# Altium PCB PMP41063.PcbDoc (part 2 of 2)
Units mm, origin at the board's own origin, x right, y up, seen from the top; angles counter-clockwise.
Board outline 173.28 x 60.81 mm, 2 copper layers (Top Layer, Bottom Layer), stack 1.575 mm thick; 103 components, 53 nets, 215 pads, 774 vias.
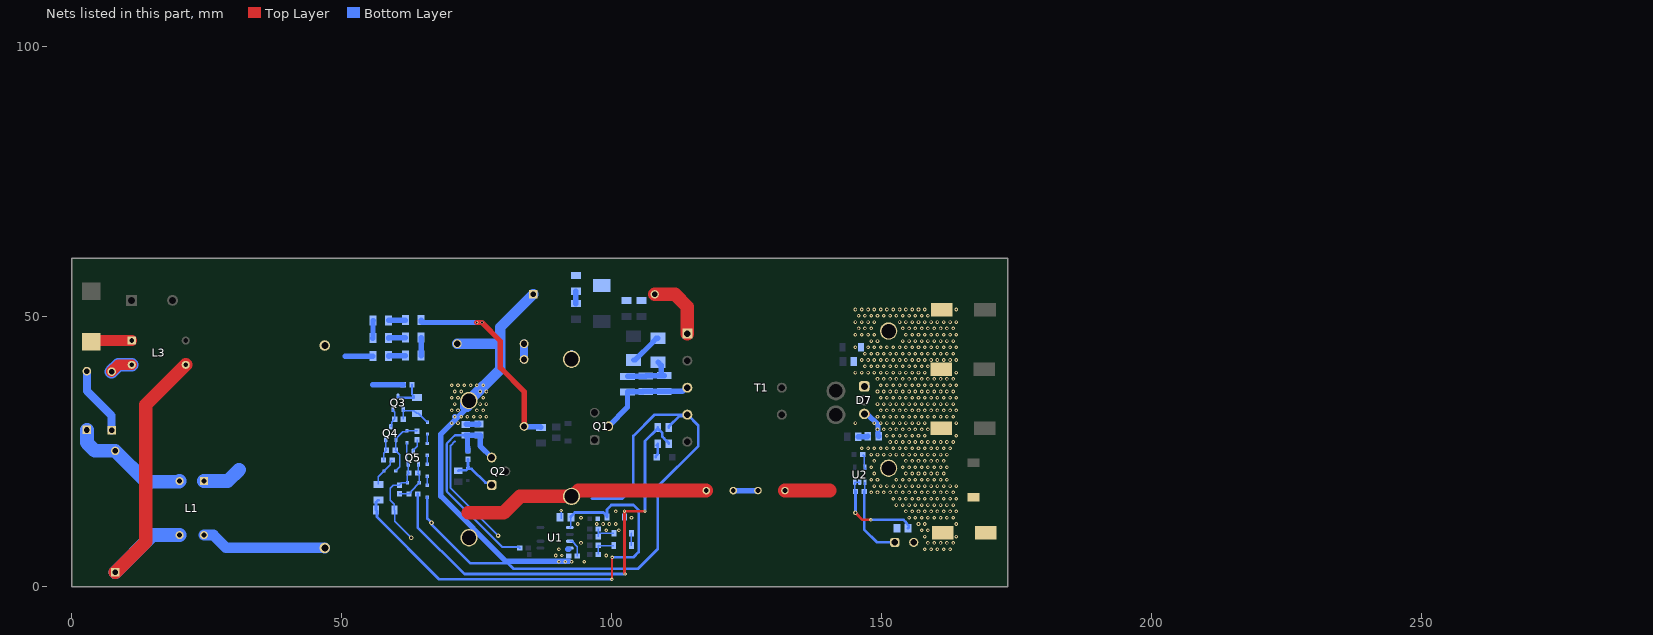
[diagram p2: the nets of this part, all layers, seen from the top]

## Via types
v1: diameter 0.66, hole 0.33, Top Layer to Bottom Layer, 760 vias
v2: diameter 0.61, hole 0.203, Top Layer to Bottom Layer, tented both sides, 8 vias
v3: diameter 0.864, hole 0.406, Top Layer to Bottom Layer, tented both sides, 4 vias
v4: diameter 0.6, hole 0.3, Top Layer to Bottom Layer, 2 vias

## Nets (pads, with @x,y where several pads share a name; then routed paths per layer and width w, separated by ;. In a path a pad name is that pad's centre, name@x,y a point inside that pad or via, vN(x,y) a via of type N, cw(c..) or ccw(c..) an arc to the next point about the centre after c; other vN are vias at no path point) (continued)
NetC9_2: C9.2 C17.1 | length 4.6
  Bottom Layer w1: C9.2@122.485,17.776 122.489,17.779 127.058,17.779 C17.1@127.061,17.782
NetC10_1: C10.1 Q3.3 R45.2 | length 5.7
  Bottom Layer w0.4: Q3.3@60.4,35.221 60.4,35.088 60.5,34.988 63.351,34.988 63.351,35.236 62.972,35.616 R45.2@62.972,37.393
NetC10_2: C10.2 D13.1 Q3.1 R38.1 | length 7.6
  Bottom Layer w0.254: R38.1@61.353,30.982 61.35,30.986 Q3.1@61.35,32.782 ; D13.1@65.867,30.442 65.715,30.595 65.618,30.595 65.256,30.957 65.256,30.981 64.149,32.088 C10.2@63.874,32.088 63.351,32.611 Q3.1@61.521,32.611 ; Q3.1@61.35,32.782 Q3.1@61.35,32.821 Q3.1@61.35,32.782 ; Q3.1@61.35,32.782 Q3.1@61.521,32.611 ; Q3.1@61.35,32.782 Q3.1@61.521,32.611
NetC16_2: C16.2 R27.2 | length 1.8
  Bottom Layer w1: R27.2@145.623,27.73 145.677,27.784 147.34,27.784 C16.2@147.394,27.838
NetC25_1: C25.1 D20.1 Q5.1 R9.2 R42.2 | length 8.3
  Bottom Layer w0.254: R9.2@60.66,17.186 62.403,17.186 R42.2@62.426,17.163 62.451,17.163 62.799,17.511 62.799,17.683 D20.1@64.326,19.21 64.326,20.734 C25.1@64.026,21.034 64.176,21.184 Q5.1@64.176,22.683
NetC33_1: C33.1 L1.3 L3.3 | length 58.6
  Top Layer w2.54: C33.1@8.02,2.633 13.665,8.278 13.665,33.668 L3.3@21.072,41.075
  Bottom Layer w2.54: C33.1@8.02,2.633 14.948,9.561 18.955,9.561 18.981,9.535 L1.3@19.935,9.535
NetC33_2: C33.2 D9.1 L1.2 | length 22.6
  Bottom Layer w2.54: D9.1@2.769,29.014 2.769,26.62 4.256,25.133 C33.2@8.02,25.133 13.721,19.431 19.831,19.431 L1.2@19.935,19.535
NetD1_2: D1.2 D2.1 | length 6.2
  Bottom Layer w1: D1.2@104.018,41.964 104.31,41.964 107.668,45.322 107.668,45.399 108.247,45.978 D2.1@108.539,45.978
NetD2_2: D2.2 R16.2 R17.2 R18.2 | length 10.2
  Bottom Layer w1: R17.2@102.9,38.944 103.674,38.944 103.712,38.982 106.266,38.982 106.329,39.046 109.027,39.046 R16.2@109.052,39.071 ; R16.2@109.682,39.071 109.261,39.071 109.111,39.221 D2.2@109.111,40.987 ; D2.2@109.111,40.987 D2.2@108.539,41.558 D2.2@109.111,40.987
NetD4_1: D4.1 R34.2 | length 3.2
  Bottom Layer w0.254: R34.2@108.113,26.046 R34.2@108.503,26.435
  Bottom Layer w0.5: D4.1@108.113,23.98 108.113,24.132 108.503,24.522 R34.2@108.503,26.435
NetD5_1: D5.1 R35.1 R36.2 | length 4.6
  Bottom Layer w0.254: R35.1@97.487,5.964 R36.2@97.487,7.659 97.54,7.607 D5.1@100.352,7.607
NetD5_2: D5.2 D12.2 | length 2.3
  Bottom Layer w0.254: D5.2@103.627,7.607 103.627,9.851 D12.2@103.652,9.876
NetD6_1: D6.1 R21.1 R22.1 | length 38.2
  Top Layer w1: v4(75.006,48.911) 75.904,48.911 79.324,45.491 79.324,40.55 83.746,36.129 D6.1@83.746,29.676
  Bottom Layer w1: R21.1@64.677,49.336 64.677,49.061 64.827,48.911 v4(75.006,48.911) v4(75.946,48.912) ; D6.1@83.746,29.676 83.831,29.591 86.777,29.591 R22.1@86.862,29.507
NetD6_2: D6.2 D10.1 | length 2.9
  Bottom Layer w1.5: D6.2@83.746,42.076 83.748,42.078 83.748,44.915 83.751,44.918 D10.1@83.751,44.985
NetD9_2: D9.2 D21.1 | length 12.8
  Bottom Layer w1.5: D9.2@2.769,39.89 2.769,36.246 7.341,31.674 D21.1@7.341,28.938
NetD11_2: D11.2 Q2.1 R26.2 R28.1 | length 9.4
  Bottom Layer w0.5: R26.2@71.558,21.455 71.633,21.529 72.985,21.529 D11.2@73.312,21.856 ; R28.1@73.335,23.585 73.335,22.335 73.447,22.222 73.362,22.137 73.362,21.906 D11.2@73.312,21.856 ; Q2.1@77.749,18.816 77.31,19.254 76.591,19.254 74.039,21.806 73.362,21.806 D11.2@73.312,21.856
NetD13_2: D13.2 D14.1 | length 1.8
  Bottom Layer w0.254: D14.1@65.791,26.505 65.829,26.543 65.829,28.204 D13.2@65.867,28.242
NetD14_2: D14.2 D17.1 | length 1.7
  Bottom Layer w0.254: D14.2@65.791,24.305 65.804,24.293 65.804,22.657 D17.1@65.816,22.644
NetD16_1: D16.1 D19.2 Q4.1 R39.1 R41.1 | length 11.3
  Bottom Layer w0.254: D19.2@59.989,21.413 60.736,22.161 60.736,24.385 60.233,24.888 60.233,24.913 59.885,25.261 R39.1@59.86,25.261 60.01,25.411 60.01,27.418 61.264,28.671 61.859,28.671 D16.1@62.032,28.844 63.865,28.844 R41.1@63.911,28.798
NetD17_2: D17.2 D18.1 | length 1.7
  Bottom Layer w0.254: D18.1@65.816,18.758 D17.2@65.816,20.444
NetD19_1: D19.1 R40.1 R43.1 | length 5.6
  Bottom Layer w0.254: R43.1@56.759,18.908 56.759,20.383 58.937,22.561 58.937,23.085 59.285,23.433 R40.1@59.31,23.433
NetD21_2: D21.2 L3.2 | length 8.5
  Top Layer w2: D21.2@7.341,39.814 8.601,41.075 L3.2@11.072,41.075
  Bottom Layer w2.54: D21.2@7.341,39.814 8.601,41.075 L3.2@11.072,41.075
NetF1_1: F1.1 L3.1 | length 7.6
  Top Layer w2: F1.1@3.556,45.32 3.811,45.575 L3.1@11.072,45.575
NetQ2_3: Q2.3 R28.2 R29.2 R32.2 R33.2 | length 52.5
  Bottom Layer w0.254: 69.478,17.678 69.478,26.444 69.478,26.563 ; 70.824,27.909 72.843,27.909 R32.2@72.954,28.02
  Bottom Layer w0.4: 69.478,26.444 69.429,26.395 69.429,17.727 69.478,17.678 69.478,17.575 79.713,7.34 82.735,7.34 R29.2@82.948,7.126 ; 69.478,26.563 70.824,27.909 70.935,28.02 R32.2@72.954,28.02
  Bottom Layer w1: R32.2@72.954,28.02 72.992,28.058 R32.2@73.081,28.058 ; R28.2@73.335,25.185 73.335,25.804 73.254,25.885 73.254,27.885 R32.2@73.081,28.058 ; Q2.3@77.749,23.896 75.595,26.049 75.595,28.058 R32.2@73.081,28.058
NetQ3_2: Q3.2 Q4.3 R38.2 | length 3.6
  Bottom Layer w0.254: Q4.3@59.06,29.63 59.219,29.789 59.219,30.473 59.728,30.982 R38.2@59.753,30.982 59.753,32.305 59.45,32.608 Q3.2@59.45,32.821
NetQ4_2: Q4.2 R39.2 R40.2 | length 4.1
  Bottom Layer w0.254: R40.2@57.71,23.433 57.71,24.736 58.235,25.261 R39.2@58.26,25.261 58.11,25.411 Q4.2@58.11,27.23
NetQ5_3: Q5.3 R41.2 | length 2.4
  Bottom Layer w0.254: Q5.3@63.226,25.083 63.226,25.283 63.911,25.969 R41.2@63.911,27.198
NetR1_1: R1.1 R5.2 | length 2.3
  Bottom Layer w1: R5.2@93.331,52.412 93.331,52.557 93.326,52.562 93.326,54.691 R1.1@93.333,54.698
NetR4_1: R4.1 R6.2 | length 3.2
  Bottom Layer w1: R4.1@58.656,42.672 58.711,42.727 61.706,42.727 R6.2@61.761,42.782
NetR6_1: R6.1 R10.2 | length 3.3
  Bottom Layer w1: R6.1@64.661,42.782 R10.2@64.661,46.106
NetR10_1: R10.1 R13.2 | length 3.2
  Bottom Layer w1: R13.2@58.626,46.023 58.667,46.065 61.72,46.065 R10.1@61.761,46.106
NetR12_2: R12.2 U1.3 | length 3.6
  Bottom Layer w0.254: U1.3@92.216,8.397 92.641,8.397 93.62,7.418 R12.2@93.62,5.634
NetR13_1: R13.1 R19.2 | length 3.3
  Bottom Layer w1: R13.1@55.726,46.023 55.749,46.046 55.749,49.255 R19.2@55.772,49.278
NetR19_1: R19.1 R21.2 | length 3.1
  Bottom Layer w1: R19.1@58.672,49.278 58.701,49.307 61.747,49.307 R21.2@61.777,49.336
NetR31_1: R31.1 U2.5 | length 3
  Bottom Layer w0.254: R31.1@146.442,24.444 146.703,24.183 146.703,22.282 U2.5@146.876,22.109 146.876,21.909 U2.5@147.049,21.736
PGND: C3.2 C6.2 C8.1 C9.1 C19.1 C24.2 C25.2 C26.1 C27.1 D10.2 D12.1 D16.2 D18.2 D20.2 HS1.1 HS1.2 HS2.1 HS2.2 L1.4 Q5.2 R3.1 R9.1 R12.1 R32.1 R33.1 R137.1 T1.4 U1.4 | length 321.9
  Top Layer w1.5: HS1.1@73.538,9.316 HS1.1@73.594,9.372
  Top Layer w2.54: HS1.2@73.233,34.32 HS1.2@73.332,34.419 ; 73.404,13.649 79.921,13.649 82.979,16.707 HS2.1@92.53,16.707 92.708,16.707 93.777,17.776 C9.1@117.485,17.776
  Bottom Layer w0.254: C3.2@59.71,14.174 59.71,15.235 58.937,16.008 58.937,18.235 59.488,18.786 R9.1@60.66,18.786 60.66,18.811 61.059,19.21 D20.2@62.126,19.21 62.126,20.734 C25.2@62.426,21.034 62.276,21.184 Q5.2@62.276,22.683 62.276,22.896 62.032,23.14 D16.2@62.032,26.644 ; C3.2@59.753,14.13 59.753,12.13 v3(62.837,9.046) ; C24.2@90.612,12.572 v2(90.612,14.093) ; R137.1@97.486,9.217 97.486,9.941 ; R3.1@97.486,10.666 97.486,9.941 ; D12.1@100.377,9.876 97.551,9.876 97.486,9.941
  Bottom Layer w0.4: 70.917,26.893 70.129,26.105 70.129,18.241 v3(78.928,9.443)
  Bottom Layer w0.5: D18.2@65.816,16.558 65.816,12.618 v3(66.604,11.831) 66.673,11.761 66.673,11.411 73.791,4.293 80.407,4.293 ; 80.407,4.685 81.79,3.302 104.826,3.302 108.503,6.979 108.503,18.511 116.018,26.026 116.018,29.791 T1.4@113.975,31.834 ; 96.317,16.304 101.954,16.304 103.98,18.33 103.98,27.871 107.943,31.834 T1.4@113.975,31.834 ; C6.2@110.532,29.457 110.532,29.622 112.486,31.576 113.717,31.576 T1.4@113.975,31.834
  Bottom Layer w1: v1(70.333,30.287) v1@70.354,30.266 ; v1(70.917,31.455) 71.23,31.142 ; 72.387,33.092 72.387,34.419 73.246,33.56 73.246,33.092 72.63,33.092 72.63,32.543 71.23,31.142 ; R32.1@72.992,30.09 75.354,30.09 R33.1@75.392,30.128 ; U1.4@91.848,6.922 U1.4@92.011,6.922 ; 92.003,4.685 91.364,4.685 C19.1@84.689,4.685 80.407,4.685 68.326,16.766 68.326,28.238 v1@70.354,30.266 ; HS2.2@92.584,43.273 HS2.2@92.605,43.273 ; v1@70.354,30.266 71.23,31.142
  Bottom Layer w1.5: D10.2@71.351,44.985 D10.2@71.351,45.025 ; HS1.2@73.246,33.092 73.538,33.384 HS1.2@73.538,34.446
  Bottom Layer w2: L1.4@24.435,9.535 26.188,9.535 28.541,7.182 46.804,7.182 C27.1@46.837,7.15 ; D10.2@71.351,44.985 79.146,44.985 ; HS1.2@73.308,34.676 HS1.2@73.538,34.446 79.324,40.232 79.324,48.034 C26.1@85.424,54.134
  other v1: 90.195,4.582 91.364,4.582 92.532,4.582 94.869,4.582 89.611,5.75 98.958,5.75 90.195,6.919 94.285,8.087 98.958,10.424 101.295,10.424 93.701,11.592 97.206,11.592 98.374,11.592 99.543,11.592 100.711,11.592 94.285,12.761 103.632,12.761 100.711,13.929 71.501,30.287 72.085,31.455 73.254,31.455 74.422,31.455 75.59,31.455 76.759,31.455 70.333,32.624 71.501,32.624 75.006,32.624 76.175,32.624 70.917,33.792 75.59,33.792 76.759,33.792 70.333,34.96 71.501,34.96 76.175,34.96 70.917,36.129 72.085,36.129 75.59,36.129 76.759,36.129 70.333,37.297 71.501,37.297 72.669,37.297 73.838,37.297 75.006,37.297 76.175,37.297
  other v2: 90.739,5.761
SGND: C11.2 C12.2 C13.2 C16.1 C17.2 C18.2 C20.2 C21.2 C22.2 D7.1 D7.3 HS3.1 HS3.2 J1.2 R30.1 U2.2 U2.3 | length 33.8
  Top Layer w0.5: v3(145.106,13.672) 146.419,12.359 v2(147.976,12.359)
  Top Layer w1: D7.3@146.758,31.987 D7.3@147.292,31.987
  Top Layer w2.54: C17.2@132.061,17.782 140.303,17.782
  Bottom Layer w0.254: C12.2@145.126,17.631 144.976,17.781 U2.3@144.976,19.359 U2.2@145.926,19.359 ; HS3.1@151.457,46.922 HS3.1@151.457,47.379
  Bottom Layer w0.5: v3@145.126,13.672 C12.2@145.126,17.631 ; v2(147.976,12.359) 154.009,12.359 154.438,11.929 154.438,11.878 154.975,11.34 154.975,10.899 R30.1@154.866,10.79 ; J1.2@155.859,8.134 J1.2@155.908,8.183
  Bottom Layer w1: D7.3@146.758,31.987 147.292,31.987 149.291,29.988 149.291,27.973 C16.1@149.426,27.838 ; D7.1@146.758,37.067 D7.1@147.292,37.067 ; J1.2@155.774,8.317 J1.2@155.908,8.183
  other v1: 157.963,6.919 159.131,6.919 160.299,6.919 161.468,6.919 162.636,6.919 158.547,8.087 159.715,8.087 160.884,8.087 162.052,8.087 163.22,8.087 157.963,9.256 163.805,9.256 157.378,10.424 158.547,10.424 156.794,11.592 157.963,11.592 163.805,11.592 155.042,12.761 156.21,12.761 157.378,12.761 158.547,12.761 159.715,12.761 160.884,12.761 162.052,12.761 163.22,12.761 154.457,13.929 155.626,13.929 156.794,13.929 157.963,13.929 159.131,13.929 160.299,13.929 161.468,13.929 162.636,13.929 163.805,13.929 152.705,15.098 153.873,15.098 155.042,15.098 156.21,15.098 157.378,15.098 158.547,15.098 159.715,15.098 160.884,15.098 162.052,15.098 163.22,15.098 152.121,16.266 153.289,16.266 154.457,16.266 155.626,16.266 156.794,16.266 157.963,16.266 159.131,16.266 160.299,16.266 161.468,16.266 162.636,16.266 163.805,16.266 148.031,17.434 149.2,17.434 150.368,17.434 151.536,17.434 152.705,17.434 153.873,17.434 155.042,17.434 156.21,17.434 157.378,17.434 158.547,17.434 159.715,17.434 160.884,17.434 162.052,17.434 163.22,17.434 148.615,18.603 149.784,18.603 150.952,18.603 152.121,18.603 153.289,18.603 154.457,18.603 155.626,18.603 156.794,18.603 157.963,18.603 159.131,18.603 160.299,18.603 161.468,18.603 162.636,18.603 163.805,18.603 148.031,19.771 149.2,19.771 152.705,19.771 153.873,19.771 155.042,19.771 156.21,19.771 157.378,19.771 158.547,19.771 159.715,19.771 160.884,19.771 162.052,19.771 148.615,20.94 154.457,20.94 155.626,20.94 156.794,20.94 157.963,20.94 159.131,20.94 160.299,20.94 161.468,20.94 148.031,22.108 153.873,22.108 155.042,22.108 156.21,22.108 157.378,22.108 158.547,22.108 159.715,22.108 160.884,22.108 162.052,22.108 148.615,23.276 154.457,23.276 155.626,23.276 156.794,23.276 157.963,23.276 159.131,23.276 160.299,23.276 161.468,23.276 148.031,24.445 149.2,24.445 150.368,24.445 151.536,24.445 152.705,24.445 153.873,24.445 155.042,24.445 156.21,24.445 157.378,24.445 158.547,24.445 159.715,24.445 160.884,24.445 162.052,24.445 146.279,25.613 147.447,25.613 148.615,25.613 149.784,25.613 150.952,25.613 152.121,25.613 153.289,25.613 154.457,25.613 155.626,25.613 156.794,25.613 157.963,25.613 159.131,25.613 160.299,25.613 161.468,25.613 162.636,25.613 151.536,26.782 152.705,26.782 153.873,26.782 155.042,26.782 156.21,26.782 157.378,26.782 158.547,26.782 159.715,26.782 160.884,26.782 162.052,26.782 163.22,26.782 150.952,27.95 152.121,27.95 153.289,27.95 154.457,27.95 155.626,27.95 156.794,27.95 157.963,27.95 163.805,27.95 149.2,29.118 150.368,29.118 151.536,29.118 152.705,29.118 153.873,29.118 155.042,29.118 156.21,29.118 157.378,29.118 158.547,29.118 145.11,30.287 148.615,30.287 149.784,30.287 150.952,30.287 152.121,30.287 153.289,30.287 154.457,30.287 155.626,30.287 156.794,30.287 157.963,30.287 163.805,30.287 149.2,31.455 150.368,31.455 151.536,31.455 152.705,31.455 153.873,31.455 155.042,31.455 156.21,31.455 157.378,31.455 158.547,31.455 159.715,31.455 160.884,31.455 162.052,31.455 163.22,31.455 149.784,32.624 150.952,32.624 152.121,32.624 153.289,32.624 154.457,32.624 155.626,32.624 156.794,32.624 157.963,32.624 159.131,32.624 160.299,32.624 161.468,32.624 162.636,32.624 163.805,32.624 149.2,33.792 150.368,33.792 151.536,33.792 152.705,33.792 153.873,33.792 155.042,33.792 156.21,33.792 157.378,33.792 158.547,33.792 159.715,33.792 160.884,33.792 162.052,33.792 163.22,33.792 149.784,34.96 150.952,34.96 152.121,34.96 153.289,34.96 154.457,34.96 155.626,34.96 156.794,34.96 157.963,34.96 159.131,34.96 160.299,34.96 161.468,34.96 162.636,34.96 163.805,34.96 149.2,36.129 150.368,36.129 151.536,36.129 152.705,36.129 153.873,36.129 155.042,36.129 156.21,36.129 157.378,36.129 158.547,36.129 159.715,36.129 160.884,36.129 162.052,36.129 163.22,36.129 149.784,37.297 150.952,37.297 152.121,37.297 153.289,37.297 154.457,37.297 155.626,37.297 156.794,37.297 157.963,37.297 159.131,37.297 160.299,37.297 161.468,37.297 162.636,37.297 163.805,37.297 149.2,38.466 150.368,38.466 151.536,38.466 152.705,38.466 153.873,38.466 155.042,38.466 156.21,38.466 157.378,38.466 158.547,38.466 159.715,38.466 160.884,38.466 162.052,38.466 163.22,38.466 145.11,39.634 146.279,39.634 147.447,39.634 148.615,39.634 149.784,39.634 150.952,39.634 152.121,39.634 153.289,39.634 154.457,39.634 155.626,39.634 156.794,39.634 157.963,39.634 163.805,39.634 146.863,40.802 148.031,40.802 149.2,40.802 150.368,40.802 151.536,40.802 152.705,40.802 153.873,40.802 155.042,40.802 156.21,40.802 157.378,40.802 158.547,40.802 146.279,41.971 147.447,41.971 148.615,41.971 149.784,41.971 150.952,41.971 152.121,41.971 153.289,41.971 154.457,41.971 155.626,41.971 156.794,41.971 157.963,41.971 159.131,41.971 160.299,41.971 161.468,41.971 162.636,41.971 163.805,41.971 146.863,43.139 148.031,43.139 149.2,43.139 150.368,43.139 151.536,43.139 152.705,43.139 153.873,43.139 155.042,43.139 156.21,43.139 157.378,43.139 158.547,43.139 159.715,43.139 160.884,43.139 162.052,43.139 163.22,43.139 145.11,44.308 147.447,44.308 148.615,44.308 149.784,44.308 150.952,44.308 152.121,44.308 153.289,44.308 154.457,44.308 155.626,44.308 156.794,44.308 157.963,44.308 159.131,44.308 160.299,44.308 161.468,44.308 162.636,44.308 163.805,44.308 148.031,45.476 149.2,45.476 153.873,45.476 155.042,45.476 156.21,45.476 157.378,45.476 158.547,45.476 159.715,45.476 160.884,45.476 162.052,45.476 163.22,45.476 145.11,46.644 146.279,46.644 147.447,46.644 148.615,46.644 154.457,46.644 155.626,46.644 156.794,46.644 157.963,46.644 159.131,46.644 160.299,46.644 161.468,46.644 162.636,46.644 163.805,46.644 145.694,47.813 146.863,47.813 148.031,47.813 153.873,47.813 155.042,47.813 156.21,47.813 157.378,47.813 158.547,47.813 159.715,47.813 160.884,47.813 162.052,47.813 163.22,47.813 145.11,48.981 146.279,48.981 147.447,48.981 148.615,48.981 153.289,48.981 154.457,48.981 155.626,48.981 156.794,48.981 157.963,48.981 159.131,48.981 160.299,48.981 161.468,48.981 162.636,48.981 163.805,48.981 145.694,50.15 146.863,50.15 148.031,50.15 149.2,50.15 150.368,50.15 151.536,50.15 152.705,50.15 153.873,50.15 155.042,50.15 156.21,50.15 157.378,50.15 158.547,50.15 145.11,51.318 146.279,51.318 147.447,51.318 148.615,51.318 149.784,51.318 150.952,51.318 152.121,51.318 153.289,51.318 154.457,51.318 155.626,51.318 156.794,51.318 157.963,51.318 163.805,51.318
SW: Q1.2 R16.1 R17.1 R18.1 T1.3 | length 19.2
  Bottom Layer w1: Q1.2@99.348,29.671 102.9,33.223 102.9,35.944 R17.1@102.9,36.044 102.939,36.082 105.76,36.082 105.848,36.171 R16.1@109.682,36.171 113.083,36.171 113.745,36.834 T1.3@113.975,36.834
Vaux_rec: C6.1 D15.2 R34.1 R42.1 | length 84.9
  Top Layer w0.5: v2(102.464,2.311) 102.464,2.341 102.357,2.448 v2(102.357,13.972) v2(106.146,13.972)
  Bottom Layer w0.254: D15.2@102.357,12.893 v2(102.357,13.972)
  Bottom Layer w0.5: R42.1@64.026,17.163 64.026,10.981 72.695,2.311 v2(102.464,2.311) ; v2(106.146,13.972) 106.146,26.937 C6.1@108.5,29.292 ; C6.1@108.5,29.457 C6.1@108.5,29.292 ; R34.1@110.535,26.435 110.535,26.6 109.688,27.447 109.688,27.463 109.347,27.804 109.347,28.445 C6.1@108.5,29.292
VDD: C3.1 C24.1 D15.1 R43.2 U1.1 | length 86.2
  Top Layer w0.4: v2(100,1.347) 100,5.201 100.031,5.232 100.031,5.381 v2(100.071,5.421)
  Bottom Layer w0.254: C24.1@92.41,12.831 U1.1@92.41,11.097 ; U1.1@92.25,10.937 U1.1@92.216,10.937 U1.1@92.25,10.937 ; U1.1@92.25,10.937 U1.1@92.41,11.097 ; U1.1@92.25,10.937 U1.1@92.41,11.097
  Bottom Layer w0.5: C3.1@56.31,14.174 56.499,13.985 56.499,12.877 68.029,1.347 v2(100,1.347) ; C3.1@56.369,14.304 56.31,14.363 56.31,15.608 56.71,16.008 R43.2@56.759,16.008 ; C24.1@92.41,12.831 92.41,12.996 93.141,13.726 98.401,13.726 98.874,13.253 99.082,13.045 D15.1@99.082,12.893 ; D15.1@99.082,13.253 99.082,14.276 99.897,15.091 101.28,15.091 104.009,15.091 104.954,14.147 104.954,6.377 104.004,5.427 100.078,5.427 v2(100.071,5.421)
VIN: C1.1 C2.1 C26.2 C27.2 D22.2 L1.1 R1.2 R4.2 R45.1 T1.1 | length 30.8
  Top Layer w2.54: C26.2@107.924,54.134 111.675,54.134 113.975,51.834 T1.1@113.975,46.834
  Bottom Layer w1: 50.571,42.672 R4.2@55.756,42.672 ; 55.726,37.393 R45.1@61.372,37.393 ; T1.1@113.55,47.259 T1.1@113.975,46.834
  Bottom Layer w2.54: L1.1@24.435,19.535 28.857,19.535 30.937,21.615
VOUT: C12.1 C22.1 J1.1 L2.2 R30.2 U2.1 | length 15.5
  Bottom Layer w0.254: C12.1@146.726,17.631 146.876,17.781 U2.1@146.876,19.359
  Bottom Layer w0.5: C12.1@146.726,17.631 146.726,10.61 149.154,8.183 J1.1@152.408,8.183
pads on no net: T1.2 T1.7 T1.8 U1.8 U2.4
copper on no net: | length 927.9
  Top Layer w0.381: 199.885,78.054 210.297,78.054 233.913,78.054 255.751,78.054 272.256,78.054 286.731,78.054 ; 199.885,81.102 210.297,81.102 233.913,81.102 255.751,81.102 272.256,81.102 286.731,81.102 ; 199.885,84.15 210.297,84.15 233.913,84.15 255.751,84.15 272.256,84.15 286.731,84.15 ; 199.885,87.198 210.297,87.198 233.913,87.198 255.751,87.198 272.256,87.198 286.731,87.198 ; 199.885,90.246 210.297,90.246 233.913,90.246 255.751,90.246 272.256,90.246 286.731,90.246 ; 199.885,93.294 210.297,93.294 233.913,93.294 255.751,93.294 272.256,93.294 286.731,93.294 ; 199.885,96.342 286.731,96.342 ; 210.297,99.39 210.297,75.006 ; 233.913,99.39 233.913,75.006 ; 255.751,99.39 255.751,75.006 ; 272.256,99.39 272.256,75.006 ; 210.297,75.006 199.885,75.006 199.885,99.39 286.731,99.39 286.731,75.006 272.256,75.006 ; 210.297,75.006 233.913,75.006 ; 233.913,75.006 255.751,75.006 ; 255.751,75.006 272.256,75.006

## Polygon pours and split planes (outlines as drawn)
PGND on Top Layer "TOP_LAYER_PGND_P010" (solid, remove dead copper, pour order 10): 29.693,58.725 30.404,59.436 93.927,59.436 96.332,57.792 96.332,39.236 88.206,39.292 88.206,49.488 84.961,52.732 75.078,52.728 72.387,49.602 72.387,42.384 77.521,37.19 77.521,30.121 72.387,25.385 72.387,18.392 79.934,9.794 79.934,1.753 29.693,1.753
FLYB on Top Layer "TOP_LAYER_FLYB_P000" (solid, remove dead copper, pour order 0): 139.275,32.691 140.317,33.733 142.479,33.733 144.385,35.639 147.984,35.639 148.285,35.339 148.285,33.733 147.948,33.396 145.228,33.396 143.547,31.715 143.547,30.823 142.687,29.963 140.168,29.963 139.275,30.856
FLYA on Top Layer "TOP_LAYER_FLYA_P001" (solid, remove dead copper, pour order 1): 139.172,58.577 140.771,60.176 170.878,60.176 172.547,58.508 172.547,21.416 172.623,21.34 171.836,20.552 164.572,20.552 163.708,21.416 163.708,24.87 165.232,26.394 165.232,52.094 163.932,53.395 144.815,53.395 143.591,52.171 143.591,37.494 143.591,35.511 142.277,34.196 139.77,34.196 139.172,34.794
SGND on Top Layer "TOP_LAYER_SGND_P002" (solid, remove dead copper, pour order 2): 144.203,51.784 144.203,31.472 142.719,29.988 139.319,29.988 139.319,16.667 150.48,16.667 154.716,12.491 154.716,9.148 154.716,7.421 155.58,6.557 162.844,6.557 164.521,8.233 164.521,18.47 162.844,20.146 162.844,25.239 164.521,26.915 164.521,51.79 163.374,52.937 145.357,52.937
VOUT on Top Layer "TOP_LAYER_VOUT_P009" (solid, remove dead copper, pour order 9): 165.232,18.47 165.232,8.335 162.987,6.09 154.98,6.09 153.947,7.124 153.947,10.156 153.583,10.519 150.652,10.519 150.043,9.91 150.043,2.747 151.821,0.969 169.549,0.969 172.623,4.044 172.623,18.432 172.585,18.47
PGND on Top Layer "TOP_LAYER_PGND_P017" (solid, remove dead copper, pour order 17): 104.445,15.961 100.787,16.009 100.756,14.717 87.782,14.696 87.782,1.347 104.445,1.347 104.445,14.961
VOUT on Bottom Layer "BOTTOM_LAYER_VOUT_P018" (solid, remove dead copper, pour order 18): 165.211,18.463 165.211,7.35 163.322,5.461 155.068,5.461 153.583,6.945 153.583,11.582 150.022,11.582 150.022,2.74 151.8,0.962 169.528,0.962 172.603,4.037 172.603,18.425 172.565,18.463
SW on Bottom Layer "BOTTOM_LAYER_SW_P016" (solid, remove dead copper, pour order 16): 100.197,31.908 100.406,32.068 98.324,29.986 98.324,29.199 98.824,28.699 99.667,28.699 105.912,34.945 113.811,34.945 115.189,36.323 115.189,37.29 114.481,37.998 113.309,37.998 112.145,36.834 101.326,36.834 101.326,34.945 101.326,33.038
FLYB on Bottom Layer "BOTTOM_LAYER_FLYB_P003" (solid, remove dead copper, pour order 3): 139.319,33.109 139.835,33.624 142.389,33.624 144.404,35.639 147.984,35.639 148.329,35.295 148.329,33.758 147.992,33.421 145.272,33.421 143.591,31.741 143.591,30.848 142.731,29.988 140.212,29.988 139.319,30.881
VIN on Bottom Layer "BOTTOM_LAYER_VIN_P012" (solid, remove dead copper, pour order 12): 47.371,31.906 47.371,18.517 29.693,18.517 29.693,31.906 29.693,58.242 31.623,60.173 113.111,60.173 116.108,57.175 116.108,45.72 111.782,45.788 111.782,50.342 110.019,51.918 95.631,51.918 95.631,56.617 84.988,56.617 81.357,52.985 54.484,52.985 51.211,49.713 51.211,40.335 53.828,37.871 55.772,37.871 55.772,31.906
SGND on Bottom Layer "BOTTOM_LAYER_SGND_P005" (solid, remove dead copper, pour order 5): 144.061,38.332 144.061,35.329 144.061,23.35 144.061,18.417 147.675,18.417 147.675,12.7 154.009,12.7 154.008,7.424 155.341,6.09 162.959,6.09 164.419,7.651 164.517,18.417 163.183,20.237 163.225,25.378 164.775,26.928 164.775,52.158 163.825,53.108 145.563,53.108 144.061,51.606
FLYA on Bottom Layer "BOTTOM_LAYER_FLYA_P004" (solid, remove dead copper, pour order 4): 139.273,58.679 140.771,60.176 170.878,60.176 172.649,58.406 172.649,21.416 172.725,21.34 171.625,20.24 164.985,20.24 163.81,21.416 163.81,24.87 165.334,26.394 165.334,52.53 164.209,53.655 145.075,53.655 143.591,52.171 143.591,37.596 143.591,35.511 142.468,34.387 140.155,34.387 139.273,35.269
PGND on Bottom Layer "BOTTOM_LAYER_PGND_P011" (solid, remove dead copper, pour order 11): 89.154,14.717 89.154,3.937 106.101,3.937 106.101,14.717
PGND on Bottom Layer "BOTTOM_LAYER_PGND_P013" (solid, remove dead copper, pour order 13): 71.501,11.37 71.501,10.372 71.409,8.087 72.547,6.948 72.574,6.975 75.062,6.975 75.748,7.661 75.748,9.987 74.365,11.37

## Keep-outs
Keep-Out Layer:
  lines w0.254: 76.632,21.387 78.41,21.387 79.934,22.911 79.934,24.994 79.146,24.994 79.146,23.241 78.13,22.225 76.632,22.225 76.632,21.387 ; 95.944,29.957 95.944,30.795 97.442,30.795 98.458,31.811 98.458,33.564 99.246,33.564 99.246,31.55 97.653,29.957 95.944,29.957 ; 100.762,26.238 102.21,26.238 102.21,28.177 107.497,33.464 115.4,33.464 116.018,33.464 116.018,34.519 106.673,34.519 105.618,33.464 100.762,28.607 100.762,26.238
  text ".Layer_Name" at -3.531,-103.543 h1.52

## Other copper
Top Layer:
  text "Layer" at 201.663,97.104 h1.52
  text "Name" at 212.075,97.104 h1.52
  text "Material" at 235.691,97.104 h1.52
  text "Thickness" at 257.529,97.104 h1.52
  text "Constant" at 274.034,97.104 h1.52
  text "Top Overlay" at 212.075,94.056 h1.52
  text "Top Solder" at 212.075,91.008 h1.52
  text "Solder Resist" at 235.691,91.008 h1.52
  text "0.010mm" at 257.529,91.008 h1.52
  text "3.5" at 274.034,91.008 h1.52
  text "1" at 201.663,87.96 h1.52
  text "Top Layer" at 212.075,87.96 h1.52
  text "0.036mm" at 257.529,87.96 h1.52
  text "Dielectric1" at 212.075,84.912 h1.52
  text "FR-4 High Tg" at 235.691,84.912 h1.52
  text "1.504mm" at 257.529,84.912 h1.52
  text "4.8" at 274.034,84.912 h1.52
  text "2" at 201.663,81.864 h1.52
  text "Bottom Layer" at 212.075,81.864 h1.52
  text "0.036mm" at 257.529,81.864 h1.52
  text "Bottom Solder" at 212.075,78.816 h1.52
  text "Solder Resist" at 235.691,78.816 h1.52
  text "0.010mm" at 257.529,78.816 h1.52
  text "3.5" at 274.034,78.816 h1.52
  text "Bottom Overlay" at 212.075,75.768 h1.52
  text "Total board thickness:" at 201.663,72.72 h1.52
  text "1.595mm" at 257.529,72.72 h1.52
  text ".Layer_Name" at -3.531,-103.543 h1.52
Bottom Layer:
  rectangle net PGND: 90.276,15.091 94.869,19.333
  rectangle net AUX: 113.052,25.798 114.979,28.092
  rectangle net PGND: 90.194,40.557 95.02,44.606
  rectangle net PGND: 116.362,16.917 118.674,18.698
  rectangle net SGND: 131.094,16.815 133.406,18.597
  rectangle net PGND: 69.867,29.292 77.309,38.078
  pour cut-out: 144.061,22.94 144.061,18.935 147.661,18.935 147.661,22.94
  pour cut-out: 97.088,5.026 97.088,3.667 103.611,3.667 103.611,5.026
  pour cut-out: 86.004,11.831 86.004,7.894 92.812,7.894 92.812,11.831
  text ".Layer_Name" at -3.531,-103.543 h1.52

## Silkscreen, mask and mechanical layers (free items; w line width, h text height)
Top Overlay:
  text "'.PRJ_Number'.PCB_Rev" at 118.535,4.851 h1.3
  text ".Layer_Name" at -3.531,-103.543 h1.52
Bottom Overlay:
  text ".Layer_Name" at -3.531,-103.543 h1.52
Top Paste:
  text ".Layer_Name" at -3.531,-103.543 h1.52
Bottom Paste:
  text ".Layer_Name" at -3.531,-103.543 h1.52
Top Solder:
  text ".Layer_Name" at -3.531,-103.543 h1.52
  text ".Layer_Name" at -3.531,-103.543 h1.52
Bottom Solder:
  text ".Layer_Name" at -3.531,-103.543 h1.52
Drill Guide:
  text ".Layer_Name" at -3.531,-103.543 h1.52
M1 Board Outline:
  the board outline again, w0.254
  text ".Layer_Name" at -3.531,-103.543 h1.52
M2 Board Dimensions:
  rectangle: -15.011,-91.897 -5.486,-88.722
  rectangle: -18.186,-88.722 -15.011,-85.547
  lines w0.178: -18.186,-88.722 7.214,-88.722 ; -15.011,-91.897 -15.011,-85.547 ; -11.836,-91.897 -11.836,-85.547 ; -5.486,-91.897 -5.486,-85.547 ; 0.864,-91.897 0.864,-85.547 ; -18.186,-91.897 -18.186,-85.547 7.214,-85.547 7.214,-91.897 -18.186,-91.897
  text ".Layer_Name" at -3.531,-103.543 h1.52
M3 3D STEP Top:
  text ".Layer_Name" at -3.531,-103.543 h1.52
M4 3D STEP Bottom:
  text ".Layer_Name" at -3.531,-103.543 h1.52
Top M5 Assembly Top/M6 Assembly Bottom:
  lines w0.254: -25.603,-105.363 142.037,-105.363 ; -25.603,-100.199 142.088,-100.199 ; -25.603,-95.034 -25.603,-110.528 76.124,-110.528 142.088,-110.528 142.088,-95.034 -25.591,-95.034 -25.591,-110.528 14.427,-110.528 ; 37.008,-110.528 37.008,-95.034 ; 69.19,-100.199 69.19,-95.034 ; 90.526,-100.199 90.526,-95.034 ; 106.324,-110.693 106.324,-105.541
  text "COMPONENTS MARKED 'DNP' SHOULD NOT BE POPULATED." at 11.112,-89.827 h1.52
  text "ASSEMBLY VARIANT:" at 11.1,-92.761 h1.52
  text ".VariantName" at 37.414,-92.761 h1.52
  text "PCB VIEWED FROM TOP SIDE" at -23.99,-98.391 h1.52
  text "BOARD #:" at 38.913,-98.391 h1.52
  text ".PRJ_Number" at 52.768,-98.391 h1.52
  text "REV:" at 74.219,-98.391 h1.52
  text ".PCB_Rev" at 81.623,-98.391 h1.52
  text "SVN REV:" at 95.504,-98.391 h1.52
  text ".VersionControl_RevNumber" at 108.356,-98.391 h1.52
  text "PLOT NAME =" at -23.99,-108.771 h1.52
  text ".plot_File_Name" at -3.531,-108.771 h1.52
  text "GENERATED    :" at 38.964,-108.771 h1.52
  text ".Print_Date" at 61.049,-108.771 h1.52
  text ".Print_Time" at 79.565,-108.771 h1.52
  text "TEXAS INSTRUMENTS" at 111.684,-108.771 h1.52
Bottom M5 Assembly Top/M6 Assembly Bottom:
  lines w0.254: -25.616,-100.211 142.075,-100.211 ; -25.565,-105.376 142.075,-105.376 ; 10.147,-110.706 10.147,-105.554 ; 25.946,-100.211 25.946,-95.047 ; 47.282,-100.211 47.282,-95.047 ; 79.464,-110.541 79.464,-95.047 ; 102.044,-110.541 142.062,-110.541 142.062,-95.047 -25.616,-95.047 -25.616,-110.541 40.348,-110.541 142.075,-110.541 142.075,-95.047
  text "COMPONENTS MARKED 'DNP' SHOULD NOT BE POPULATED." at 136.804,-89.814 h1.52
  text ".VariantName" at 110.287,-92.761 h1.52
  text "ASSEMBLY VARIANT:" at 136.677,-92.761 h1.52
  text ".VersionControl_RevNumber" at 8.115,-98.404 h1.52
  text "SVN REV:" at 20.968,-98.404 h1.52
  text ".PCB_Rev" at 34.849,-98.404 h1.52
  text "REV:" at 42.253,-98.404 h1.52
  text ".PRJ_Number" at 63.703,-98.404 h1.52
  text "BOARD #:" at 77.559,-98.404 h1.52
  text "PCB VIEWED FROM BOTTOM SIDE" at 140.462,-98.404 h1.52
  text "TEXAS INSTRUMENTS" at 4.788,-108.784 h1.52
  text ".Print_Time" at 36.906,-108.784 h1.52
  text ".Print_Date" at 55.423,-108.784 h1.52
  text "GENERATED    :" at 77.508,-108.784 h1.52
  text ".plot_File_Name" at 120.002,-108.784 h1.52
  text "PLOT NAME =" at 140.462,-108.784 h1.52
M9 Title Sheet:
  drawing of 56 lines, arcs and shapes, not listed
  text "1" at 8.695,258.15 h1.78
  text "2" at 93.167,258.15 h1.78
  text "3" at 177.749,258.15 h1.78
  text "4" at 262.458,258.15 h1.78
  text "5" at 346.913,258.15 h1.78
  text "6" at 431.622,258.15 h1.78
  text "A" at -29.947,212.989 h1.78
  text "A" at 470.433,212.989 h1.78
  text "B" at -29.947,117.739 h1.78
  text "B" at 470.433,117.739 h1.78
  text "C" at -29.947,22.489 h1.78
  text "C" at 470.433,22.489 h1.78
  text "D" at -29.947,-72.761 h1.78
  text "D" at 470.433,-72.761 h1.78
  text "PROJECT TITLE:" at 391.846,-74.92 h1.14
  text ".PRJ_Title" at 393.116,-78.307 h1.78
  text "DESIGNED FOR:" at 391.846,-82.565 h1.14
  text ".PRJ_Customer" at 393.116,-86.121 h1.78
  text "FILE NAME:" at 391.846,-90.185 h1.14
  text ".PCB_File_Name_No_Path" at 393.116,-93.233 h1.78
  text "Texas Instruments (TI) and/or its licensors do not warrant the accuracy or completeness of this specification" at 265.62,-97.344 h1.14
  text "ENGINEER:" at 391.846,-97.551 h1.14
  text "LAYOUT BY:" at 430.073,-97.551 h1.14
  text "or any information contained therein. TI and/or its licensors do not warrant that this design will meet" at 264.478,-100.206 h1.14
  text ".PRJ_Engineer" at 393.116,-101.488 h1.78
  text ".PCB_Layout" at 431.355,-101.488 h1.78
  text "the specifications, will be suitable for your application or fit for any particular purpose, or will operate in" at 264.478,-103.068 h1.14
  text ".Layer_Name" at -3.531,-103.543 h1.52
  text "ALTIUM DESIGNER VERSION:" at 430.073,-105.425 h1.14
  text "an implementation. TI and/or its licensors do not warrant that the design is production worthy. You should" at 264.478,-105.929 h1.14
  text "completely validate and test your design implementation to confirm the system functionality for your application." at 265.62,-108.791 h1.14
  text ".print_Scale" at 393.116,-108.812 h1.78
  text ".Application_BuildNumber" at 431.355,-108.812 h1.78
  text "1" at 8.695,-115.23 h1.78
  text "2" at 93.167,-115.23 h1.78
  text "3" at 177.749,-115.23 h1.78
  text "4" at 262.458,-115.23 h1.78
  text "5" at 346.913,-115.23 h1.78
  text "6" at 431.622,-115.23 h1.78
M10 Fab Notes:
  drawing of 189 lines, arcs and shapes, not listed
  text "DESIGN INFORMATION" at 418.135,79.938 h1.52
  text "MIN. TRACK WIDTH:" at 401.763,76.582 h1.52
  text "8" at 429.608,76.582 h1.52
  text "MIL" at 433.539,76.582 h1.52
  text "MIN. CLEARANCE:" at 401.763,73.429 h1.52
  text "MIL" at 433.539,73.429 h1.52
  text "7.874" at 425.289,73.313 h1.52
  text "MIN. VIA PAD SIZE:" at 401.763,70.277 h1.52
  text "24" at 428.846,70.277 h1.52
  text "MIL" at 433.539,70.277 h1.52
  text "0.05mm (2MIL)" at 419.416,66.977 h1.52
  text "MINIMUM ANNULAR RING" at 393.401,66.768 h1.52
  text "EXTERNAL" at 437.4,66.768 h1.52
  text "PER" at 398.481,63.971 h1.52
  text "IPC-D-275 CLASS 2 LEVEL C" at 404.069,63.971 h1.52
  text "MIL, HOLES" at 441.87,61.419 h1.52
  text "+/-" at 431.902,61.201 h1.52
  text "+/-" at 453.593,61.201 h1.52
  text "REGISTRATION TOLERANCES:" at 393.401,61.174 h1.52
  text "METAL" at 423.875,61.174 h1.52
  text "5" at 438.511,61.174 h1.52
  text "3" at 459.669,61.174 h1.52
  text "MIL" at 462.622,61.174 h1.52
  text "HOLE SIZE TOLERANCE (UNLESS OTHERWISE SPECIFIED):" at 393.401,58.677 h1.52
  text "+/-" at 453.593,58.604 h1.52
  text "3" at 459.669,58.577 h1.52
  text "MIL" at 462.622,58.577 h1.52
  text "MATERIAL:" at 391.502,55.08 h1.52
  text "FR-4 High Tg" at 416.558,51.816 h1.52
  text "X" at 412.889,51.613 h1.52
  text "FR-4" at 402.195,51.498 h1.52
  text "OTHER" at 439.99,51.498 h1.52
  text "62 MIL (1.6mm) +/-10%" at 410.326,47.865 h1.52
  text "X" at 407.275,47.803 h1.52
  text "THICKNESS:" at 393.401,47.656 h1.52
  text "OTHER" at 442.962,47.656 h1.52
  text "TOLERANCE:" at 393.401,44.143 h1.52
  text "X" at 414.946,44.143 h1.52
  text "ANSI IPC-6012 TYPE 3 CLASS 2" at 419.468,44.143 h1.52
  text "OTHER +/-" at 419.467,40.481 h1.52
  text "BOW & TWIST:" at 393.401,36.793 h1.52
  text "X" at 414.946,36.793 h1.52
  text "ANSI IPC-6012 TYPE 3 CLASS 2" at 419.468,36.793 h1.52
  text "OTHER +/-" at 419.467,33.067 h1.52
  text "DRILLING:" at 391.502,29.749 h1.52
  text "NC_DRILL FILES" at 436.231,27.077 h1.52
  text "REFERENCE:" at 393.401,26.977 h1.52
  text "X" at 410.095,26.975 h1.52
  text "AS SHOWN" at 414.616,26.977 h1.52
  text "X" at 432.98,26.977 h1.52
  text "OTHER" at 443.8,23.364 h1.52
  text "PTH COPPER THICKNESS:" at 393.393,23.275 h1.52
  text "X" at 422.329,23.275 h1.52
  text "20-30 um" at 425.58,23.275 h1.52
  text "BOARD FINISH:" at 391.502,19.526 h1.52
  text "SILKSCREEN:" at 395.444,16.728 h1.52
  text "X" at 419.772,16.728 h1.52
  text "TOP" at 422.744,16.728 h1.52
  text "X" at 432.726,16.728 h1.52
  text "BOTTOM" at 435.723,16.728 h1.52
  text "SILKSCREEN COLOR:" at 395.444,12.787 h1.52
  text "X" at 419.747,12.787 h1.52
  text "WHITE" at 422.744,12.787 h1.52
  text "OTHER" at 435.723,12.787 h1.52
  text "X" at 423.074,9.143 h1.52
  text "GREEN" at 426.071,9.143 h1.52
  text "OTHER" at 441.768,9.143 h1.52
  text "SOLDER RESIST COLOR:" at 395.444,8.969 h1.52
  text "X" at 423.074,5.225 h1.52
  text "MATTE" at 426.071,5.225 h1.52
  text "SEMI-GLOSS" at 441.757,5.209 h1.52
  text "IMMERSION GOLD (ENIG)" at 418.451,0.837 h1.52
  text "ENEPIG" at 452.425,0.653 h1.52
  text "SURFACE FINISH:" at 391.502,0.628 h1.52
  text "X" at 413.93,0.628 h1.52
  text "IMM. TIN/SILVER OR EQUIV" at 399.872,-2.86 h1.52
  text "OTHER" at 436.231,-2.96 h1.52
  text "ARRAY/PANEL:" at 391.502,-6.907 h1.52
  text "CUT AND TRIM PER M1 BOARD OUTLINE" at 418.451,-7.115 h1.52
  text "N.C. ROUTE" at 418.451,-10.569 h1.52
  text "X" at 435.927,-10.569 h1.52
  text "V. SCORE" at 440.448,-10.569 h1.52
  text "CERTIFICATION:" at 391.502,-13.849 h1.52
  text "MATERIALS AND WORKMANSHIP FOR ALL PCBS" at 409.917,-13.849 h1.52
  text "TO MEET OR EXCEED THE REQUIREMENTS OF:" at 409.917,-16.238 h1.52
  text "X" at 400.71,-19.505 h1.52
  text "ANSI IPC-A-600F CLASS ->" at 403.961,-19.505 h1.52
  text "X" at 445.82,-19.505 h1.52
  text "2" at 448.614,-19.505 h1.52
  text "1" at 440.613,-19.543 h1.52
  text "3" at 457.605,-19.543 h1.52
  text "X" at 421.334,-23.256 h1.52
  text "RoHS" at 424.585,-23.256 h1.52
  text "OTHER" at 440.953,-23.256 h1.52
  text "PER ORDER" at 451.039,-23.256 h1.52
  text "ALL BOARDS MUST MEET OR EXCEED UL94-V0 REQUIREMENTS." at 392.201,-27.164 h1.52
  text "PCB MUST BEAR THE UL94V-0 UL REGISTERED MATERIAL ID NUMBER" at 392.201,-30.112 h1.52
  text "ADDITIONAL REQUIREMENTS:" at 391.502,-34.415 h1.52
  text "MICROSECTION:" at 393.401,-37.136 h1.52
  text "YES" at 416.407,-37.136 h1.52
  text "REQUIRED" at 438.289,-40.802 h1.52
  text "BARE BOARD ELEC. TEST:" at 393.401,-40.875 h1.52
  text "NONE" at 426.567,-40.875 h1.52
  text "X" at 435.292,-40.875 h1.52
  text "PER ORDER" at 453.325,-40.875 h1.52
  text "XX MIL VIAS REQUIRE NON-CONDUCTIVE FILL AND PLANARIZE" at 397.672,-46.08 h1.5
  text "XX MIL VIAS REQUIRE CONDUCTIVE FILL AND PLANARIZE" at 397.875,-48.721 h1.52
  text "OUTER XX MIL TRACES REQUIRE 50 OHM SINGLE-ENDED IMPEDANCE" at 397.85,-52.871 h1.47
  text "LAYER 2 & 3 (INNER LAYERS) XX MIL WIDE, XX MIL SPACE / TRACES REQUIRE 100 OHM DIFFERENTIAL IMPEDANCE" at 397.647,-58.858 h1.52
  text ".Layer_Name" at -3.531,-103.543 h1.52
M11 Gerber Information:
  lines w0.254: -25.603,-105.363 142.037,-105.363 ; -25.603,-100.199 142.088,-100.199 ; -25.603,-95.034 -25.603,-110.528 76.124,-110.528 142.088,-110.528 142.088,-95.034 -25.591,-95.034 -25.591,-110.528 14.427,-110.528 ; 37.008,-110.528 37.008,-95.034 ; 69.19,-100.199 69.19,-95.034 ; 90.526,-100.199 90.526,-95.034 ; 106.324,-110.693 106.324,-105.541
  text "ALL ARTWORK VIEWED FROM TOP SIDE" at -23.99,-98.391 h1.52
  text "BOARD #:" at 38.913,-98.391 h1.52
  text ".PRJ_Number" at 52.768,-98.391 h1.52
  text "REV:" at 74.219,-98.391 h1.52
  text ".PCB_Rev" at 81.623,-98.391 h1.52
  text "SVN REV:" at 95.504,-98.391 h1.52
  text ".VersionControl_RevNumber" at 108.356,-98.391 h1.52
  text "LAYER NAME =" at -23.99,-103.543 h1.52
  text "PLOT NAME =" at -23.99,-108.771 h1.52
  text ".plot_File_Name" at -3.531,-108.771 h1.52
  text "GENERATED    :" at 38.964,-108.771 h1.52
  text ".Print_Date" at 61.049,-108.771 h1.52
  text ".Print_Time" at 79.565,-108.771 h1.52
  text "TEXAS INSTRUMENTS" at 111.684,-108.771 h1.52
M12 Stackup:
  drawing of 191 lines, arcs and shapes, not listed
  text "Layer" at 352.782,250.786 h1.52
  text "Name" at 363.194,250.786 h1.52
  text "Material" at 386.809,250.786 h1.52
  text "Thickness" at 408.647,250.786 h1.52
  text "Constant" at 425.153,250.786 h1.52
  text "Board Layer Stack" at 439.628,250.786 h1.52
  text "Top Overlay" at 363.194,247.738 h1.52
  text "Top Solder" at 363.194,244.69 h1.52
  text "Solder Resist" at 386.809,244.69 h1.52
  text "0.40mil" at 408.647,244.69 h1.52
  text "3.5" at 425.153,244.69 h1.52
  text "1" at 352.782,241.642 h1.52
  text "Top Layer" at 363.194,241.642 h1.52
  text "1.40mil" at 408.647,241.642 h1.52
  text "Dielectric1" at 363.194,238.594 h1.52
  text "FR-4 High Tg" at 386.809,238.594 h1.52
  text "59.20mil" at 408.647,238.594 h1.52
  text "4.8" at 425.153,238.594 h1.52
  text "2" at 352.782,235.546 h1.52
  text "Bottom Layer" at 363.194,235.546 h1.52
  text "1.40mil" at 408.647,235.546 h1.52
  text "Bottom Solder" at 363.194,232.498 h1.52
  text "Solder Resist" at 386.809,232.498 h1.52
  text "0.40mil" at 408.647,232.498 h1.52
  text "3.5" at 425.153,232.498 h1.52
  text "Bottom Overlay" at 363.194,229.45 h1.52
  text ".Layer_Name" at -3.531,-103.543 h1.52
M13 Component Bodies Top:
  text ".Layer_Name" at -3.531,-103.543 h1.52
M14 Component Bodies Bottom:
  text ".Layer_Name" at -3.531,-103.543 h1.52
M15 Courtyards Top:
  text ".Layer_Name" at -3.531,-103.543 h1.52
M16 Courtyards Bottom:
  text ".Layer_Name" at -3.531,-103.543 h1.52
Drill Drawing:
  drawing of 154 lines, arcs and shapes, not listed
  text "Symbol" at 202.351,48.813 h1.83
  text "Count" at 209.986,48.813 h1.83
  text "Hole Size" at 217.643,48.813 h1.83
  text "Plated" at 232.627,48.813 h1.83
  text "Hole Type" at 239.209,48.813 h1.83
  text "Drill Layer Pair" at 248.738,48.813 h1.83
  text "Hole Tolerance" at 267.136,48.813 h1.83
  text "8" at 209.986,45.655 h1.52
  text "8.00mil (0.203mm)" at 217.643,45.655 h1.52
  text "PTH" at 232.627,45.655 h1.52
  text "Round" at 239.209,45.655 h1.52
  text "Top Layer - Bottom Layer" at 248.738,45.655 h1.52
  text "2" at 209.986,42.498 h1.52
  text "11.81mil (0.300mm)" at 217.643,42.498 h1.52
  text "PTH" at 232.627,42.498 h1.52
  text "Round" at 239.209,42.498 h1.52
  text "Top Layer - Bottom Layer" at 248.738,42.498 h1.52
  text "760" at 209.986,39.34 h1.52
  text "13.00mil (0.330mm)" at 217.643,39.34 h1.52
  text "PTH" at 232.627,39.34 h1.52
  text "Round" at 239.209,39.34 h1.52
  text "Top Layer - Bottom Layer" at 248.738,39.34 h1.52
  text "4" at 209.986,36.182 h1.52
  text "16.00mil (0.406mm)" at 217.643,36.182 h1.52
  text "PTH" at 232.627,36.182 h1.52
  text "Round" at 239.209,36.182 h1.52
  text "Top Layer - Bottom Layer" at 248.738,36.182 h1.52
  text "12" at 209.986,33.024 h1.52
  text "35.43mil (0.900mm)" at 217.643,33.024 h1.52
  text "PTH" at 232.627,33.024 h1.52
  text "Round" at 239.209,33.024 h1.52
  text "Top Layer - Bottom Layer" at 248.738,33.024 h1.52
  text "4" at 209.986,29.867 h1.52
  text "39.37mil (1.000mm)" at 217.643,29.867 h1.52
  text "PTH" at 232.627,29.867 h1.52
  text "Round" at 239.209,29.867 h1.52
  text "Top Layer - Bottom Layer" at 248.738,29.867 h1.52
  text "4" at 209.986,26.709 h1.52
  text "41.34mil (1.050mm)" at 217.643,26.709 h1.52
  text "PTH" at 232.627,26.709 h1.52
  text "Round" at 239.209,26.709 h1.52
  text "Top Layer - Bottom Layer" at 248.738,26.709 h1.52
  text "4" at 209.986,23.551 h1.52
  text "45.28mil (1.150mm)" at 217.643,23.551 h1.52
  text "PTH" at 232.627,23.551 h1.52
  text "Round" at 239.209,23.551 h1.52
  text "Top Layer - Bottom Layer" at 248.738,23.551 h1.52
  text "2" at 209.986,20.394 h1.52
  text "47.24mil (1.200mm)" at 217.643,20.394 h1.52
  text "PTH" at 232.627,20.394 h1.52
  text "Round" at 239.209,20.394 h1.52
  text "Top Layer - Bottom Layer" at 248.738,20.394 h1.52
  text "+7.87mil/-0.00mil" at 267.136,20.394 h1.52
  text "7" at 209.986,17.236 h1.52
  text "49.21mil (1.250mm)" at 217.643,17.236 h1.52
  text "PTH" at 232.627,17.236 h1.52
  text "Round" at 239.209,17.236 h1.52
  text "Top Layer - Bottom Layer" at 248.738,17.236 h1.52
  text "13" at 209.986,14.078 h1.52
  text "51.18mil (1.300mm)" at 217.643,14.078 h1.52
  text "PTH" at 232.627,14.078 h1.52
  text "Round" at 239.209,14.078 h1.52
  text "Top Layer - Bottom Layer" at 248.738,14.078 h1.52
  text "2" at 209.986,10.92 h1.52
  text "98.43mil (2.500mm)" at 217.643,10.92 h1.52
  text "PTH" at 232.627,10.92 h1.52
  text "Round" at 239.209,10.92 h1.52
  text "Top Layer - Bottom Layer" at 248.738,10.92 h1.52
  text "6" at 209.986,7.763 h1.52
  text "105.12mil (2.670mm)" at 217.643,7.763 h1.52
  text "PTH" at 232.627,7.763 h1.52
  text "Round" at 239.209,7.763 h1.52
  text "Top Layer - Bottom Layer" at 248.738,7.763 h1.52
  text "828 Total" at 209.986,4.605 h1.52
  text ".Layer_Name" at -3.531,-103.543 h1.52
M17 Embedded Cavity:
  text ".Layer_Name" at -3.531,-103.543 h1.52
M18 Embedded Assembly:
  text ".Layer_Name" at -3.531,-103.543 h1.52
M19 Embedded Keepout:
  text ".Layer_Name" at -3.785,-103.543 h1.52

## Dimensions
0,0 to 1.854,60.808 on M2 Board Dimensions
0,0 to 173.284,0 on M2 Board Dimensions
-18.186,-91.897 to 7.214,-91.897 on M2 Board Dimensions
